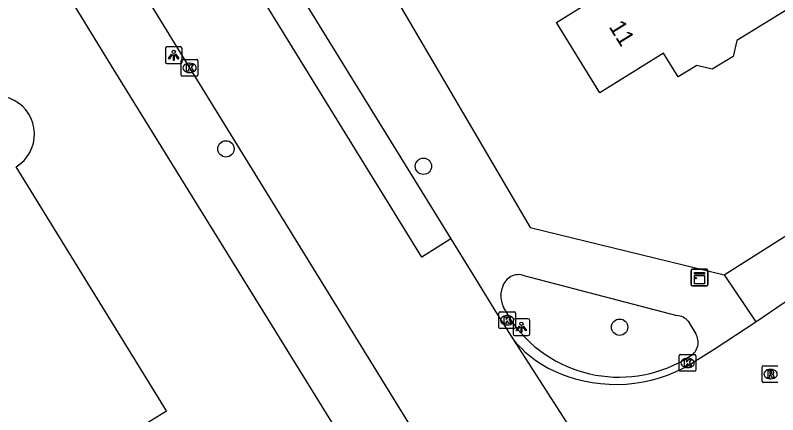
# Model space of a CAD drawing. Extents: x 161354 to 161876, y 382161 to 382804.
# Drawn here: x 161550.65 to 161596.32, y 382475.55 to 382499.48 of the extents above; entities that cross this region are included whole.
import ezdxf

# ---------------------------------------------------------------- set-up
doc = ezdxf.new("R2010")
doc.units = 0
for name, color, linetype in [('IMGEO_Boom', 7, 'Continuous'), ('IMGEO_Kast', 7, 'Continuous'), ('IMGEO_Kolk', 7, 'Continuous'), ('IMGEO_Lichtpunt', 7, 'Continuous'), ('IMGEO_Pand', 7, 'Continuous'), ('IMGEO_Pand_nummerreeks', 7, 'Continuous'), ('IMGEO_Rijbaan_lokaal_gesloten', 7, 'Continuous'), ('IMGEO_Rijbaan_lokaal_open', 7, 'Continuous'), ('IMGEO_Rioolput', 7, 'Continuous'), ('IMGEO_Voetpad_open', 7, 'Continuous')]:
    doc.layers.add(name, color=color, linetype=linetype)

msp = doc.modelspace()

# ---------------------------------------------------------------- linework, layer by layer
at = {"layer": 'IMGEO_Boom'}
for centre in [(161563.273, 382491.48), (161575.102, 382490.437), (161586.85, 382480.8)]:
    msp.add_circle(centre, 0.489, dxfattribs=at)
at = {"layer": 'IMGEO_Kast'}
for p, q in [((161591.13, 382483.351), (161591.13, 382484.192)), ((161591.13, 382484.192), (161591.13, 382483.351)), ((161591.205, 382484.276), (161592.046, 382484.276)), ((161592.046, 382484.276), (161591.205, 382484.276)), ((161592.13, 382484.201), (161592.13, 382483.36)), ((161592.13, 382483.36), (161592.13, 382484.201)), ((161592.055, 382483.276), (161591.214, 382483.276)), ((161591.214, 382483.276), (161592.055, 382483.276))]:
    msp.add_line(p, q, dxfattribs=at)
for points in [[(161591.325, 382484.066), (161591.925, 382484.066), (161591.925, 382483.981), (161591.325, 382483.981), (161591.325, 382484.066)], [(161591.325, 382483.891), (161591.925, 382483.891), (161591.925, 382483.402), (161591.325, 382483.402), (161591.325, 382483.891)]]:
    msp.add_lwpolyline(points, dxfattribs=at)
msp.add_circle((161591.409, 382483.74), 0.0377, dxfattribs=at)
for centre, start, end in [((161591.208, 382484.198), 92.4484, 184.2845), ((161591.208, 382484.198), 92.4484, 184.2845), ((161592.052, 382484.198), 2.4484, 94.2845), ((161592.052, 382484.198), 2.4484, 94.2845), ((161591.208, 382483.354), 182.4484, 274.2845), ((161591.208, 382483.354), 182.4484, 274.2845), ((161592.052, 382483.354), 272.4484, 4.2845), ((161592.052, 382483.354), 272.4484, 4.2845)]:
    msp.add_arc(centre, 0.0779, start, end, dxfattribs=at)
at = {"layer": 'IMGEO_Kolk'}
for p, q in [((161560.666, 382496.829), (161561.518, 382496.829)), ((161560.591, 382495.903), (161560.591, 382496.755)), ((161561.079, 382496.609), (161561.104, 382496.609)), ((161561.592, 382496.755), (161561.592, 382495.903)), ((161561.102, 382496.049), (161561.077, 382496.049)), ((161561.518, 382495.829), (161560.666, 382495.829)), ((161579.613, 382480.787), (161579.613, 382481.639)), ((161579.688, 382481.713), (161580.54, 382481.713)), ((161580.101, 382481.493), (161580.126, 382481.493)), ((161580.614, 382481.639), (161580.614, 382480.787)), ((161580.124, 382480.933), (161580.099, 382480.933)), ((161580.54, 382480.713), (161579.688, 382480.713)), ((161590.416, 382478.23), (161590.416, 382479.082)), ((161590.491, 382479.156), (161591.343, 382479.156)), ((161591.417, 382479.082), (161591.417, 382478.23)), ((161590.904, 382478.936), (161590.929, 382478.936)), ((161591.343, 382478.156), (161590.491, 382478.156)), ((161590.927, 382478.376), (161590.902, 382478.376))]:
    msp.add_line(p, q, dxfattribs=at)
for points in [[(161560.666, 382496.829), (161561.518, 382496.829)], [(161560.591, 382495.903), (161560.591, 382496.755)], [(161560.912, 382496.529), (161561.035, 382496.529), (161561.035, 382496.378), (161561.165, 382496.529), (161561.329, 382496.529), (161561.183, 382496.378), (161561.336, 382496.129), (161561.184, 382496.129), (161561.099, 382496.293), (161561.035, 382496.226), (161561.035, 382496.129), (161560.912, 382496.129), (161560.912, 382496.529)], [(161561.592, 382496.755), (161561.592, 382495.903)], [(161561.518, 382495.829), (161560.666, 382495.829)], [(161579.613, 382480.787), (161579.613, 382481.639)], [(161579.688, 382481.713), (161580.54, 382481.713)], [(161579.934, 382481.413), (161580.057, 382481.413), (161580.057, 382481.262), (161580.187, 382481.413), (161580.351, 382481.413), (161580.205, 382481.262), (161580.358, 382481.013), (161580.206, 382481.013), (161580.121, 382481.177), (161580.057, 382481.11), (161580.057, 382481.013), (161579.934, 382481.013), (161579.934, 382481.413)], [(161580.614, 382481.639), (161580.614, 382480.787)], [(161580.54, 382480.713), (161579.688, 382480.713)], [(161590.416, 382478.23), (161590.416, 382479.082)], [(161590.491, 382479.156), (161591.343, 382479.156)], [(161591.417, 382479.082), (161591.417, 382478.23)], [(161590.737, 382478.856), (161590.86, 382478.856), (161590.86, 382478.705), (161590.99, 382478.856), (161591.154, 382478.856), (161591.008, 382478.705), (161591.161, 382478.456), (161591.009, 382478.456), (161590.924, 382478.62), (161590.86, 382478.553), (161590.86, 382478.456), (161590.737, 382478.456), (161590.737, 382478.856)], [(161591.343, 382478.156), (161590.491, 382478.156)]]:
    msp.add_lwpolyline(points, dxfattribs=at)
for centre, start, end in [((161560.668, 382496.753), 91.552, 178.448), ((161560.668, 382496.753), 91.552, 178.448), ((161561.516, 382496.753), 1.552, 88.448), ((161561.516, 382496.753), 1.552, 88.448), ((161560.668, 382495.905), 181.552, 268.448), ((161560.668, 382495.905), 181.552, 268.448), ((161561.516, 382495.905), 271.552, 358.448), ((161561.516, 382495.905), 271.552, 358.448), ((161579.69, 382481.637), 91.552, 178.448), ((161579.69, 382481.637), 91.552, 178.448), ((161580.538, 382481.637), 1.552, 88.448), ((161580.538, 382481.637), 1.552, 88.448), ((161579.69, 382480.789), 181.552, 268.448), ((161579.69, 382480.789), 181.552, 268.448), ((161580.538, 382480.789), 271.552, 358.448), ((161580.538, 382480.789), 271.552, 358.448), ((161590.493, 382479.08), 91.552, 178.448), ((161590.493, 382479.08), 91.552, 178.448), ((161591.341, 382479.08), 1.552, 88.448), ((161591.341, 382479.08), 1.552, 88.448), ((161590.493, 382478.232), 181.552, 268.448), ((161590.493, 382478.232), 181.552, 268.448), ((161591.341, 382478.232), 271.552, 358.448), ((161591.341, 382478.232), 271.552, 358.448)]:
    msp.add_arc(centre, 0.0765, start, end, dxfattribs=at)
for centre, major_axis, ratio, start_param, end_param in [((161561.078, 382496.329), (-0.387, 0.002), 0.722429, 4.712389, 7.853982), ((161561.103, 382496.329), (-0.39, 0.002), 0.717154, 1.570796, 4.712389), ((161580.1, 382481.213), (-0.387, 0.002), 0.722429, 4.712389, 7.853982), ((161580.125, 382481.213), (-0.39, 0.002), 0.717154, 1.570796, 4.712389), ((161590.903, 382478.656), (-0.387, 0.002), 0.722429, 4.712389, 7.853982), ((161590.928, 382478.656), (-0.39, 0.002), 0.717154, 1.570796, 4.712389)]:
    msp.add_ellipse(centre, major_axis=major_axis, ratio=ratio, start_param=start_param, end_param=end_param, dxfattribs=at)
at = {"layer": 'IMGEO_Lichtpunt'}
for p, q in [((161559.645, 382497.486), (161559.645, 382496.679)), ((161559.645, 382497.486), (161559.645, 382496.679)), ((161560.547, 382497.581), (161559.739, 382497.581)), ((161560.547, 382497.581), (161559.739, 382497.581)), ((161560.641, 382496.679), (161560.641, 382497.486)), ((161560.641, 382496.679), (161560.641, 382497.486)), ((161559.739, 382496.585), (161560.547, 382496.585)), ((161559.739, 382496.585), (161560.547, 382496.585)), ((161581.372, 382481.3), (161580.564, 382481.3)), ((161581.372, 382481.3), (161580.564, 382481.3)), ((161580.47, 382481.205), (161580.47, 382480.398)), ((161580.47, 382481.205), (161580.47, 382480.398)), ((161581.466, 382480.398), (161581.466, 382481.205)), ((161581.466, 382480.398), (161581.466, 382481.205)), ((161580.564, 382480.304), (161581.372, 382480.304)), ((161580.564, 382480.304), (161581.372, 382480.304))]:
    msp.add_line(p, q, dxfattribs=at)
for points in [[(161560.019, 382497.15), (161560.058, 382497.122), (161559.87, 382496.86), (161559.832, 382496.887), (161560.019, 382497.15)], [(161560.121, 382497.102), (161560.168, 382497.102), (161560.168, 382496.78), (161560.121, 382496.78), (161560.121, 382497.102)], [(161560.231, 382497.122), (161560.269, 382497.149), (161560.456, 382496.887), (161560.417, 382496.859), (161560.231, 382497.122)], [(161580.844, 382480.869), (161580.883, 382480.841), (161580.695, 382480.579), (161580.657, 382480.606), (161580.844, 382480.869)], [(161580.946, 382480.821), (161580.993, 382480.821), (161580.993, 382480.499), (161580.946, 382480.499), (161580.946, 382480.821)], [(161581.056, 382480.841), (161581.094, 382480.868), (161581.281, 382480.606), (161581.242, 382480.578), (161581.056, 382480.841)]]:
    msp.add_lwpolyline(points, dxfattribs=at)
for centre in [(161560.144, 382497.284), (161580.969, 382481.003)]:
    msp.add_circle(centre, 0.0994, dxfattribs=at)
for centre, start, end in [((161559.739, 382497.486), 90, 180), ((161559.739, 382497.486), 90, 180), ((161560.547, 382497.486), 0, 90), ((161560.547, 382497.486), 0, 90), ((161559.739, 382496.679), 180, 270), ((161559.739, 382496.679), 180, 270), ((161560.547, 382496.679), 270, 0), ((161560.547, 382496.679), 270, 360), ((161580.564, 382481.205), 90, 180), ((161580.564, 382481.205), 90, 180), ((161581.372, 382481.205), 0, 90), ((161581.372, 382481.205), 0, 90), ((161580.564, 382480.398), 180, 270), ((161580.564, 382480.398), 180, 270), ((161581.372, 382480.398), 270, 0), ((161581.372, 382480.398), 270, 360)]:
    msp.add_arc(centre, 0.0946, start, end, dxfattribs=at)
at = {"layer": 'IMGEO_Pand'}
for points in [[(161597.174, 382500), (161593.876, 382497.975), (161593.651, 382497.019), (161592.397, 382496.245), (161591.465, 382496.465), (161590.363, 382495.784), (161589.486, 382497.203), (161585.66, 382494.839), (161583.063, 382499.041), (161584.604, 382500), (161584.77, 382500.103), (161581.642, 382505.102), (161583.577, 382506.313)], [(161551.092, 382470.489), (161559.71, 382475.789), (161550.708, 382490.406)]]:
    msp.add_lwpolyline(points, dxfattribs=at)
msp.add_arc((161549.514, 382492.361), 2.29, 301.4111, 122.1038, dxfattribs=at)
at = {"layer": 'IMGEO_Rijbaan_lokaal_gesloten'}
for points in [[(161577.112, 382470.322), (161575.449, 382473.073), (161561.101, 382496.334), (161558.843, 382500), (161550.097, 382514.2), (161540.821, 382529.326)], [(161576.74, 382486.091), (161575.005, 382484.986), (161551.177, 382523.64), (161552.932, 382524.704)], [(161576.74, 382486.091), (161578.221, 382483.705), (161579.506, 382481.572), (161580.5, 382480.035)], [(161580.5, 382480.035), (161591.554, 382462.823)]]:
    msp.add_lwpolyline(points, dxfattribs=at)
at = {"layer": 'IMGEO_Rijbaan_lokaal_open'}
for points in [[(161594.999, 382481.125), (161596.698, 382482.276), (161598.444, 382483.37), (161608.438, 382489.731), (161613.115, 382492.645)], [(161591.558, 382478.875), (161592.518, 382479.481), (161594.999, 382481.125)]]:
    msp.add_lwpolyline(points, dxfattribs=at)
for centre, radius, start, end in [((161585.958, 382484.65), 7.147, 220.2139, 251.5666), ((161586.625, 382486.208), 8.838, 250.6576, 303.9296)]:
    msp.add_arc(centre, radius, start, end, dxfattribs=at)
at = {"layer": 'IMGEO_Rioolput'}
for p, q in [((161595.393, 382477.567), (161595.393, 382478.419)), ((161595.468, 382478.493), (161596.32, 382478.493)), ((161595.881, 382478.273), (161595.906, 382478.273)), ((161595.904, 382477.713), (161595.879, 382477.713)), ((161596.32, 382477.493), (161595.468, 382477.493))]:
    msp.add_line(p, q, dxfattribs=at)
for points in [[(161595.393, 382477.567), (161595.393, 382478.419)], [(161595.468, 382478.493), (161596.32, 382478.493)], [(161595.982, 382478.191), (161595.73, 382478.193), (161595.73, 382477.793)], [(161595.908, 382478.112), (161595.854, 382478.112), (161595.854, 382478.031)], [(161595.73, 382477.793), (161595.854, 382477.793), (161595.854, 382477.955), (161595.865, 382477.955)], [(161595.854, 382478.031), (161595.906, 382478.031)], [(161595.912, 382477.926), (161595.983, 382477.793), (161596.123, 382477.793), (161596.058, 382477.919)], [(161596.32, 382477.493), (161595.468, 382477.493)]]:
    msp.add_lwpolyline(points, dxfattribs=at)
for centre, radius, start, end in [((161595.47, 382478.417), 0.0765, 91.552, 178.448), ((161595.47, 382478.417), 0.0765, 91.552, 178.448), ((161595.914, 382478.016), 0.0964, 77.0061, 93.1865), ((161595.928, 382478.073), 0.0378, 276.6634, 79.6772), ((161595.981, 382478.081), 0.109, 350.3612, 89.416), ((161595.864, 382477.902), 0.0533, 26.0293, 88.6989), ((161595.89, 382478.22), 0.19, 274.7715, 282.9687), ((161595.979, 382478.081), 0.112, 277.5842, 350.9817), ((161595.963, 382477.866), 0.108, 29.5134, 73.7905), ((161595.47, 382477.569), 0.0765, 181.552, 268.448), ((161595.47, 382477.569), 0.0765, 181.552, 268.448)]:
    msp.add_arc(centre, radius, start, end, dxfattribs=at)
for centre, major_axis, ratio, start_param, end_param in [((161595.88, 382477.993), (-0.387, 0.002), 0.722429, 4.712389, 7.853982), ((161595.905, 382477.993), (-0.39, 0.002), 0.717154, 1.570796, 4.712389)]:
    msp.add_ellipse(centre, major_axis=major_axis, ratio=ratio, start_param=start_param, end_param=end_param, dxfattribs=at)
at = {"layer": 'IMGEO_Voetpad_open'}
for points in [[(161537.341, 382557.85), (161565.95, 382511.235), (161572.292, 382501.343), (161572.851, 382501.493), (161573.727, 382500), (161581.489, 382486.772), (161593.113, 382483.942)], [(161537.314, 382527.427), (161542.448, 382519.098), (161554.214, 382500), (161556.561, 382496.19), (161570.48, 382473.695), (161567.506, 382461.215)], [(161552.932, 382524.704), (161576.74, 382486.091)], [(161593.113, 382483.942), (161618.484, 382500), (161639.588, 382513.357)], [(161581.03, 382483.923), (161590.273, 382481.492)], [(161593.113, 382483.942), (161594.999, 382481.125)], [(161579.735, 382482.734), (161579.818, 382483.122)], [(161580.476, 382481.013), (161579.89, 382482.004)], [(161590.96, 382481.155), (161591.408, 382480.402)]]:
    msp.add_lwpolyline(points, dxfattribs=at)
for centre, radius, start, end in [((161580.81, 382482.938), 1.009, 77.409, 169.5117), ((161581.324, 382482.69), 1.589, 178.4097, 205.5653), ((161590.23, 382480.535), 0.958, 40.3359, 87.4046), ((161586.811, 382485.67), 7.863, 216.3188, 303.0041), ((161590.599, 382479.894), 0.956, 301.2184, 32.1369)]:
    msp.add_arc(centre, radius, start, end, dxfattribs=at)

# ---------------------------------------------------------------- texts
at = {"layer": 'IMGEO_Pand_nummerreeks'}
msp.add_text('11', height=1, rotation=301.7187, dxfattribs=at).set_placement((161586.179, 382498.794))

doc.saveas('drawing.dxf')
